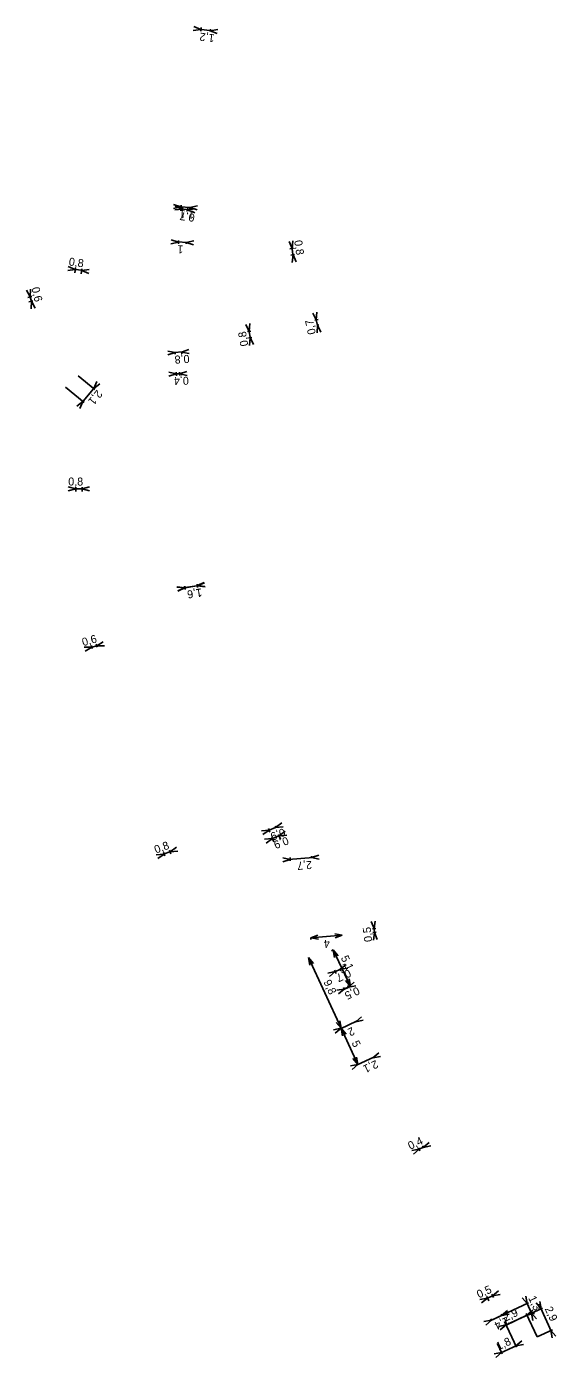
# Model space of a CAD drawing. Extents: x -732085 to -731961, y -1048713 to -1047966.
# Drawn here: x -732071.5 to -732005.2, y -1048521.1 to -1048354.8 of the extents above; entities that cross this region are included whole.
import ezdxf

# ---------------------------------------------------------------- set-up
doc = ezdxf.new("R2010")
doc.units = 0
doc.layers.add('Kota_NN', color=7, linetype='Continuous')
doc.layers.add('Kota_VN', color=7, linetype='Continuous')

msp = doc.modelspace()

# ---------------------------------------------------------------- linework, layer by layer
at = {"layer": 'Kota_NN'}
for p, q in [((-732052, -1048377.63), (-732052.96, -1048377.75)), ((-732052, -1048377.63), (-732052.89, -1048377.26)), ((-732051.15, -1048377.74), (-732052.2, -1048377.6)), ((-732052.02, -1048377.78), (-732051.98, -1048377.43)), ((-732051.37, -1048377.86), (-732051.32, -1048377.52)), ((-732051.35, -1048377.72), (-732050.4, -1048377.6)), ((-732051.35, -1048377.72), (-732050.46, -1048378.09)), ((-732038.31, -1048382.57), (-732038.69, -1048381.68)), ((-732038.31, -1048382.57), (-732038.2, -1048381.61)), ((-732038.57, -1048382.6), (-732038.11, -1048382.54)), ((-732038.45, -1048383.4), (-732037.99, -1048383.33)), ((-732038.34, -1048382.37), (-732038.16, -1048383.56)), ((-732038.19, -1048383.36), (-732038.3, -1048384.32)), ((-732038.19, -1048383.36), (-732037.81, -1048384.24)), ((-732065.38, -1048385.19), (-732066.33, -1048385.31)), ((-732065.38, -1048385.19), (-732066.27, -1048384.82)), ((-732065.58, -1048385.16), (-732064.39, -1048385.32)), ((-732065.44, -1048385.62), (-732065.35, -1048384.99)), ((-732064.64, -1048385.73), (-732064.56, -1048385.1)), ((-732064.58, -1048385.3), (-732063.63, -1048385.18)), ((-732064.58, -1048385.3), (-732063.7, -1048385.67)), ((-732071, -1048388.61), (-732071.46, -1048387.76)), ((-732071.31, -1048388.68), (-732070.81, -1048388.56)), ((-732071.05, -1048388.42), (-732070.82, -1048389.35)), ((-732071, -1048388.61), (-732070.98, -1048387.65)), ((-732071.18, -1048389.23), (-732070.68, -1048389.11)), ((-732070.87, -1048389.15), (-732070.9, -1048390.11)), ((-732070.87, -1048389.15), (-732070.41, -1048390)), ((-732043.66, -1048392.91), (-732044.07, -1048392.04)), ((-732043.66, -1048392.91), (-732043.58, -1048391.95)), ((-732043.46, -1048392.88), (-732043.86, -1048392.95)), ((-732043.33, -1048393.66), (-732043.72, -1048393.73)), ((-732043.49, -1048393.9), (-732043.7, -1048392.71)), ((-732043.52, -1048393.7), (-732043.61, -1048394.66)), ((-732043.52, -1048393.7), (-732043.12, -1048394.57)), ((-732065.03, -1048398.45), (-732062.93, -1048400.17)), ((-732052.77, -1048398.21), (-732053.7, -1048397.99)), ((-732052.77, -1048398.21), (-732053.69, -1048398.49)), ((-732052.15, -1048398.2), (-732052.97, -1048398.22)), ((-732052.76, -1048398.45), (-732052.77, -1048398.02)), ((-732052.35, -1048398.2), (-732051.43, -1048397.93)), ((-732052.34, -1048398.44), (-732052.35, -1048398)), ((-732052.35, -1048398.2), (-732051.41, -1048398.42)), ((-732066.62, -1048399.89), (-732064.27, -1048401.81)), ((-732062.96, -1048399.89), (-732064.55, -1048401.84)), ((-732063.08, -1048400.04), (-732062.69, -1048399.17)), ((-732063.08, -1048400.04), (-732062.31, -1048399.48)), ((-732064.43, -1048401.68), (-732065.2, -1048402.24)), ((-732064.43, -1048401.68), (-732064.82, -1048402.56)), ((-732065.33, -1048412.58), (-732066.26, -1048412.82)), ((-732065.33, -1048412.58), (-732066.25, -1048412.32)), ((-732065.53, -1048412.58), (-732064.33, -1048412.58)), ((-732065.33, -1048412.93), (-732065.33, -1048412.38)), ((-732064.53, -1048412.58), (-732063.6, -1048412.33)), ((-732064.53, -1048412.93), (-732064.53, -1048412.38)), ((-732064.53, -1048412.58), (-732063.61, -1048412.83)), ((-732051.72, -1048424.95), (-732052.68, -1048424.86)), ((-732051.72, -1048424.95), (-732052.59, -1048425.35)), ((-732049.95, -1048424.65), (-732051.92, -1048424.98)), ((-732051.72, -1048424.97), (-732051.75, -1048424.75)), ((-732050.14, -1048424.7), (-732050.18, -1048424.48)), ((-732050.14, -1048424.68), (-732049.27, -1048424.28)), ((-732050.14, -1048424.68), (-732049.19, -1048424.77)), ((-732062.65, -1048432.37), (-732062.76, -1048432)), ((-732062.7, -1048432.19), (-732061.88, -1048431.7)), ((-732063.31, -1048432.36), (-732064.27, -1048432.37)), ((-732063.31, -1048432.36), (-732064.13, -1048432.85)), ((-732063.5, -1048432.42), (-732062.51, -1048432.14)), ((-732063.26, -1048432.54), (-732063.36, -1048432.17)), ((-732062.7, -1048432.19), (-732061.74, -1048432.18)), ((-732040.77, -1048456.26), (-732041.73, -1048456.36)), ((-732040.77, -1048456.26), (-732041.55, -1048456.83)), ((-732039.74, -1048455.86), (-732040.96, -1048456.34)), ((-732040.6, -1048456.7), (-732040.84, -1048456.08)), ((-732039.76, -1048456.37), (-732040, -1048455.75)), ((-732039.93, -1048455.94), (-732039.15, -1048455.37)), ((-732039.93, -1048455.94), (-732038.97, -1048455.84)), ((-732054.3, -1048458.21), (-732055.26, -1048458.3)), ((-732054.3, -1048458.21), (-732055.08, -1048458.77)), ((-732054.49, -1048458.28), (-732053.35, -1048457.86)), ((-732054.21, -1048458.45), (-732054.37, -1048458.02)), ((-732053.45, -1048458.17), (-732053.6, -1048457.74)), ((-732053.54, -1048457.93), (-732052.75, -1048457.37)), ((-732053.54, -1048457.93), (-732052.58, -1048457.84)), ((-732028.06, -1048467.53), (-732028.41, -1048466.63)), ((-732028.06, -1048467.53), (-732027.91, -1048466.58)), ((-732028.26, -1048467.55), (-732027.86, -1048467.51)), ((-732028.21, -1048468.02), (-732027.81, -1048467.98)), ((-732028.01, -1048468), (-732028.15, -1048468.95)), ((-732027.99, -1048468.2), (-732028.08, -1048467.33)), ((-732028.01, -1048468), (-732027.66, -1048468.9)), ((-732033.39, -1048470.28), (-732033.16, -1048470.17)), ((-732033.16, -1048470.17), (-732031.02, -1048474.75)), ((-732033.16, -1048470.17), (-732032.54, -1048470.91)), ((-732033.16, -1048470.17), (-732032.99, -1048471.12)), ((-732031.78, -1048475.07), (-732032.73, -1048475.23)), ((-732031.78, -1048475.07), (-732032.52, -1048475.68)), ((-732031.09, -1048474.75), (-732031.96, -1048475.15)), ((-732031.76, -1048475.11), (-732031.87, -1048474.89)), ((-732031.76, -1048475.09), (-732031.02, -1048474.75)), ((-732031.02, -1048474.75), (-732031.64, -1048474.01)), ((-732031.24, -1048474.92), (-732031.36, -1048474.65)), ((-732031.28, -1048474.83), (-732030.54, -1048474.21)), ((-732031.28, -1048474.83), (-732030.33, -1048474.66)), ((-732031.02, -1048474.75), (-732031.19, -1048473.8)), ((-732022.43, -1048495.08), (-732023.37, -1048495.25)), ((-732022.43, -1048495.08), (-732023.16, -1048495.7)), ((-732022.61, -1048495.17), (-732021.74, -1048494.76)), ((-732022.5, -1048494.93), (-732022.34, -1048495.27)), ((-732021.91, -1048494.88), (-732022.01, -1048494.67)), ((-732021.93, -1048494.85), (-732021.19, -1048494.23)), ((-732021.93, -1048494.85), (-732020.98, -1048494.68)), ((-732014.08, -1048513.76), (-732013.1, -1048513.3)), ((-732013.74, -1048514.02), (-732013.99, -1048513.49)), ((-732013.17, -1048513.62), (-732013.36, -1048513.2)), ((-732013.28, -1048513.38), (-732012.54, -1048512.76)), ((-732013.28, -1048513.38), (-732012.33, -1048513.22)), ((-732013.9, -1048513.67), (-732014.85, -1048513.84)), ((-732013.9, -1048513.67), (-732014.64, -1048514.29)), ((-732011.77, -1048516.61), (-732010.27, -1048519.82)), ((-732012.63, -1048519.4), (-732012.05, -1048520.65)), ((-732012.31, -1048520.56), (-732010.17, -1048519.56)), ((-732010.36, -1048519.64), (-732009.62, -1048519.03)), ((-732010.36, -1048519.64), (-732009.41, -1048519.48)), ((-732012.13, -1048520.47), (-732013.08, -1048520.64)), ((-732012.13, -1048520.47), (-732012.87, -1048521.09))]:
    msp.add_line(p, q, dxfattribs=at)
at = {"layer": 'Kota_VN'}
for p, q in [((-732049.69, -1048355.21), (-732050.65, -1048355.34)), ((-732049.69, -1048355.21), (-732050.58, -1048354.84)), ((-732048.34, -1048355.38), (-732049.89, -1048355.18)), ((-732049.67, -1048354.97), (-732049.72, -1048355.41)), ((-732048.54, -1048355.36), (-732048.51, -1048355.16)), ((-732048.54, -1048355.35), (-732047.59, -1048355.22)), ((-732048.54, -1048355.35), (-732047.65, -1048355.72)), ((-732052.19, -1048377.36), (-732053.1, -1048377.05)), ((-732052.2, -1048377.59), (-732052.17, -1048377.16)), ((-732052.19, -1048377.36), (-732053.13, -1048377.55)), ((-732050.87, -1048377.44), (-732052.39, -1048377.35)), ((-732051.07, -1048377.42), (-732051.08, -1048377.63)), ((-732051.07, -1048377.43), (-732050.13, -1048377.24)), ((-732051.07, -1048377.43), (-732050.16, -1048377.74)), ((-732052.5, -1048381.75), (-732053.44, -1048381.96)), ((-732052.5, -1048381.75), (-732053.42, -1048381.46)), ((-732051.33, -1048381.81), (-732052.7, -1048381.74)), ((-732052.51, -1048381.98), (-732052.49, -1048381.55)), ((-732051.53, -1048381.79), (-732051.54, -1048381.99)), ((-732051.53, -1048381.8), (-732050.59, -1048381.59)), ((-732051.53, -1048381.8), (-732050.61, -1048382.09)), ((-732035.28, -1048391.48), (-732035.72, -1048390.62)), ((-732035.03, -1048391.43), (-732035.48, -1048391.52)), ((-732035.1, -1048392.34), (-732035.33, -1048391.29)), ((-732035.28, -1048391.48), (-732035.23, -1048390.52)), ((-732035.14, -1048392.14), (-732035.19, -1048393.1)), ((-732035.15, -1048392.14), (-732034.95, -1048392.1)), ((-732035.14, -1048392.14), (-732034.71, -1048393)), ((-732052.9, -1048395.56), (-732053.84, -1048395.37)), ((-732052.1, -1048395.5), (-732051.19, -1048395.19)), ((-732052.9, -1048395.56), (-732053.81, -1048395.86)), ((-732051.9, -1048395.49), (-732053.1, -1048395.57)), ((-732052.9, -1048395.55), (-732052.89, -1048395.75)), ((-732052.1, -1048395.49), (-732052.09, -1048395.7)), ((-732052.1, -1048395.5), (-732051.16, -1048395.69)), ((-732051.69, -1048424.95), (-732052.65, -1048424.84)), ((-732051.69, -1048424.95), (-732052.57, -1048425.33)), ((-732049.94, -1048424.68), (-732051.89, -1048424.97)), ((-732051.66, -1048425.16), (-732051.72, -1048424.75)), ((-732050.14, -1048424.71), (-732049.26, -1048424.33)), ((-732050.14, -1048424.7), (-732050.11, -1048424.91)), ((-732050.14, -1048424.71), (-732049.18, -1048424.82)), ((-732041.17, -1048455.21), (-732042.13, -1048455.32)), ((-732041.17, -1048455.21), (-732041.95, -1048455.78)), ((-732040.17, -1048454.82), (-732041.36, -1048455.29)), ((-732041.07, -1048455.48), (-732041.25, -1048455.03)), ((-732040.35, -1048454.91), (-732040.43, -1048454.71)), ((-732040.36, -1048454.9), (-732039.58, -1048454.33)), ((-732040.36, -1048454.9), (-732039.4, -1048454.79)), ((-732038.56, -1048458.62), (-732038.53, -1048459.07)), ((-732035.88, -1048458.67), (-732035.89, -1048458.46)), ((-732035.88, -1048458.66), (-732034.97, -1048458.34)), ((-732038.54, -1048458.87), (-732039.48, -1048458.7)), ((-732038.54, -1048458.87), (-732039.45, -1048459.19)), ((-732035.68, -1048458.65), (-732038.74, -1048458.89)), ((-732035.88, -1048458.66), (-732034.93, -1048458.84)), ((-732032.03, -1048468.34), (-732035.97, -1048468.69)), ((-732035.97, -1048468.69), (-732035.07, -1048468.36)), ((-732032.03, -1048468.34), (-732032.98, -1048468.17)), ((-732032.03, -1048468.34), (-732032.93, -1048468.67)), ((-732032.03, -1048468.33), (-732032.03, -1048468.34)), ((-732035.95, -1048468.87), (-732035.97, -1048468.69)), ((-732035.97, -1048468.69), (-732035.02, -1048468.86)), ((-732036.26, -1048471.13), (-732036.26, -1048471.13)), ((-732036.26, -1048471.13), (-732032.17, -1048479.98)), ((-732036.26, -1048471.13), (-732035.65, -1048471.87)), ((-732036.26, -1048471.13), (-732036.1, -1048472.08)), ((-732032.91, -1048472.9), (-732033.85, -1048473.07)), ((-732032.91, -1048472.9), (-732033.64, -1048473.52)), ((-732032.12, -1048472.53), (-732033.09, -1048472.98)), ((-732032.8, -1048473.13), (-732032.99, -1048472.72)), ((-732032.31, -1048472.61), (-732031.57, -1048472)), ((-732032.31, -1048472.61), (-732031.36, -1048472.45)), ((-732032.31, -1048472.61), (-732032.22, -1048472.8)), ((-732030.35, -1048479.15), (-732029.62, -1048478.53)), ((-732032.17, -1048479.98), (-732033.12, -1048480.15)), ((-732032.17, -1048479.98), (-732032.91, -1048480.6)), ((-732032.17, -1048479.98), (-732032.79, -1048479.25)), ((-732030.17, -1048479.06), (-732032.35, -1048480.07)), ((-732032.17, -1048479.98), (-732032.34, -1048479.04)), ((-732032.17, -1048479.98), (-732032.17, -1048479.98)), ((-732032.17, -1048479.98), (-732032.17, -1048479.98)), ((-732032.17, -1048479.98), (-732032.17, -1048479.98)), ((-732032.17, -1048479.98), (-732030.08, -1048484.51)), ((-732032.17, -1048479.98), (-732031.56, -1048480.72)), ((-732032.17, -1048479.98), (-732032.01, -1048480.93)), ((-732030.35, -1048479.15), (-732029.41, -1048478.98)), ((-732030.35, -1048479.15), (-732030.35, -1048479.15)), ((-732028.02, -1048483.56), (-732030.26, -1048484.6)), ((-732030.08, -1048484.51), (-732030.24, -1048483.57)), ((-732028.2, -1048483.65), (-732027.46, -1048483.03)), ((-732028.2, -1048483.65), (-732027.26, -1048483.48)), ((-732030.08, -1048484.51), (-732031.03, -1048484.68)), ((-732030.08, -1048484.51), (-732030.82, -1048485.13)), ((-732030.08, -1048484.51), (-732030.7, -1048483.77)), ((-732030.08, -1048484.51), (-732030.08, -1048484.51)), ((-732030.08, -1048484.51), (-732030.08, -1048484.51)), ((-732028.2, -1048483.65), (-732028.2, -1048483.65)), ((-732008.95, -1048514.36), (-732009.12, -1048513.42)), ((-732013.39, -1048516.44), (-732008.77, -1048514.28)), ((-732011.57, -1048517.04), (-732007.02, -1048514.95)), ((-732008.95, -1048514.36), (-732009.57, -1048513.63)), ((-732009.03, -1048514.18), (-732008.31, -1048515.74)), ((-732008.98, -1048515.8), (-732008.25, -1048515.17)), ((-732007.2, -1048515.03), (-732007.82, -1048514.29)), ((-732007.2, -1048515.03), (-732007.36, -1048514.09)), ((-732007.29, -1048514.85), (-732005.89, -1048517.89)), ((-732013.39, -1048516.45), (-732014.34, -1048516.62)), ((-732013.39, -1048516.45), (-732014.12, -1048517.07)), ((-732011.95, -1048515.76), (-732013.57, -1048516.53)), ((-732013.39, -1048516.45), (-732013.48, -1048516.26)), ((-732012.12, -1048515.86), (-732012.21, -1048515.67)), ((-732012.13, -1048515.85), (-732011.39, -1048515.23)), ((-732012.13, -1048515.85), (-732011.18, -1048515.67)), ((-732011.75, -1048517.13), (-732008.8, -1048515.71)), ((-732011.57, -1048517.04), (-732008.21, -1048515.47)), ((-732007.69, -1048518.5), (-732009.07, -1048515.62)), ((-732008.98, -1048515.8), (-732008.04, -1048515.62)), ((-732008.39, -1048515.56), (-732007.77, -1048516.29)), ((-732008.39, -1048515.56), (-732008.22, -1048516.5)), ((-732011.57, -1048517.04), (-732012.52, -1048517.22)), ((-732011.57, -1048517.04), (-732012.3, -1048517.66)), ((-732011.56, -1048517.06), (-732011.66, -1048516.86)), ((-732007.69, -1048518.5), (-732005.79, -1048517.63)), ((-732005.97, -1048517.71), (-732005.36, -1048518.45)), ((-732005.97, -1048517.71), (-732005.81, -1048518.66))]:
    msp.add_line(p, q, dxfattribs=at)

# ---------------------------------------------------------------- texts
at = {"layer": 'Kota_NN'}
for s, rotation, p in [('0,7', 172.3164, (-732050.42, -1048378.25)), ('0,8', 278.3578, (-732038.05, -1048381.59)), ('0,8', 352.3172, (-732066.24, -1048384.67)), ('0,6', 283.4629, (-732070.86, -1048387.5)), ('0,8', 100.0251, (-732043.76, -1048394.68)), ('0,4', 181.7173, (-732051.22, -1048398.57)), ('2,1', 230.753, (-732062.66, -1048400.15)), ('0,8', 359.8709, (-732066.26, -1048412.17)), ('1,6', 189.7804, (-732049.64, -1048425)), ('0,6', 15.7226, (-732064.39, -1048432.25)), ('0,8', 20.4002, (-732055.3, -1048458.16)), ('0,9', 201.0982, (-732038.97, -1048456)), ('0,5', 96.2659, (-732028.29, -1048469.13)), ('5,1', 295.0163, (-732032.25, -1048471.16)), ('0,5', 205.0113, (-732030.16, -1048474.75)), ('0,4', 25.0142, (-732023.55, -1048495.17)), ('0,5', 25.0149, (-732014.96, -1048513.73)), ('1,8', 25.0145, (-732012.54, -1048520.22))]:
    msp.add_text(s, height=1, rotation=rotation, dxfattribs=at).set_placement(p)
at = {"layer": 'Kota_VN'}
for s, rotation, p in [('1,2', 172.767, (-732047.94, -1048355.83)), ('1,1', 176.3848, (-732050.5, -1048377.87)), ('1', 177.3804, (-732051.87, -1048382.18)), ('0,7', 102.0686, (-732035.33, -1048393.19)), ('0,8', 183.7395, (-732051.15, -1048395.84)), ('1,6', 188.489, (-732049.63, -1048425.04)), ('0,9', 201.2698, (-732039.38, -1048454.95)), ('2,7', 184.4846, (-732035.86, -1048459.06)), ('4', 185.1155, (-732033.63, -1048468.89)), ('0,7', 205.1747, (-732031.24, -1048472.55)), ('9,8', 294.7787, (-732034.41, -1048474.18)), ('2', 204.7791, (-732030.79, -1048479.79)), ('5', 294.7787, (-732030.9, -1048481.78)), ('2,1', 204.7787, (-732027.85, -1048483.92)), ('1,3', 295.0383, (-732008.83, -1048513.67)), ('2,9', 25.6376, (-732011.65, -1048516.63)), ('2,9', 294.6859, (-732006.78, -1048515)), ('1,4', 205.3403, (-732011.47, -1048515.98))]:
    msp.add_text(s, height=1, rotation=rotation, dxfattribs=at).set_placement(p)

doc.saveas('drawing.dxf')
